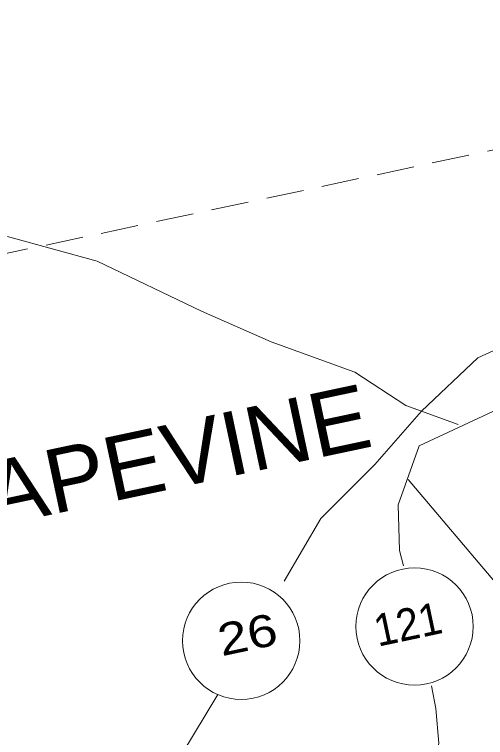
# Model space of a CAD drawing. Extents: x 2357218 to 2371708, y 6973728 to 6980157.
# Drawn here: x 2357522.9 to 2357598.1, y 6974748.1 to 6974863.5 of the extents above; entities that cross this region are included whole.
import ezdxf

# ---------------------------------------------------------------- set-up
doc = ezdxf.new("R2010")
doc.units = 0
doc.header["$LTSCALE"] = 2
doc.linetypes.add('MEDIUM_DASHED', pattern=[4.5, 3, -1.5])
doc.layers.add('62', color=7, linetype='Continuous', lineweight=13)
doc.layers.add('63', color=7, linetype='Continuous', lineweight=13)

msp = doc.modelspace()

# ---------------------------------------------------------------- linework, layer by layer
at = {"layer": '62', "linetype": 'MEDIUM_DASHED'}
msp.add_line((2357701.055, 6974863.476), (2357262.587, 6974770.278), dxfattribs=at)
at = {"layer": '62'}
for p, q in [((2357585.353, 6974801.086), (2357593.684, 6974798.028)), ((2357571.802, 6974783.024), (2357565.912, 6974773.052)), ((2357584.311, 6974777.953), (2357584.969, 6974775.514)), ((2357590.131, 6974752.736), (2357589.44, 6974756.316)), ((2357548.716, 6974744.002), (2357555.342, 6974754.934))]:
    msp.add_line(p, q, dxfattribs=at)
for points in [[(2357316.634, 6974822.183), (2357325.977, 6974829.21), (2357339.57, 6974833.985), (2357356.843, 6974830.109), (2357367.736, 6974831.46), (2357382.508, 6974827.444), (2357392.662, 6974824.794), (2357401.195, 6974823.527), (2357412.755, 6974823.776), (2357421.962, 6974824.837), (2357433.942, 6974826.923), (2357447.739, 6974830.408), (2357465.936, 6974831.929), (2357477.637, 6974833.588), (2357491.11, 6974834.819), (2357506.983, 6974831.471), (2357522.127, 6974827.953), (2357536.104, 6974824.115), (2357552.75, 6974816.152), (2357563.852, 6974811.216), (2357577.192, 6974806.369), (2357585.353, 6974801.086)], [(2357587.853, 6974800.146), (2357596.85, 6974808.683), (2357603.892, 6974811.906), (2357617.998, 6974823.047)], [(2357587.457, 6974794.656), (2357600.015, 6974800.5), (2357616.764, 6974801.254)], [(2357587.853, 6974800.146), (2357580.391, 6974791.637), (2357571.802, 6974783.024)], [(2357584.311, 6974777.953), (2357584.122, 6974785.231), (2357587.457, 6974794.656)], [(2357612.906, 6974746.026), (2357600.131, 6974772.25), (2357585.724, 6974789.274)], [(2357589.228, 6974739.131), (2357590.624, 6974747.179), (2357590.131, 6974752.736)]]:
    msp.add_lwpolyline(points, dxfattribs=at)
for centre in [(2357586.735, 6974765.808), (2357559.076, 6974763.534)]:
    msp.add_circle(centre, 9.364, dxfattribs=at)
at = {"layer": '63', "linetype": 'MEDIUM_DASHED'}
msp.add_line((2357701.055, 6974863.476), (2357262.587, 6974770.278), dxfattribs=at)
at = {"layer": '63'}
for p, q in [((2357585.353, 6974801.086), (2357593.684, 6974798.028)), ((2357571.802, 6974783.024), (2357565.912, 6974773.052)), ((2357584.311, 6974777.953), (2357584.969, 6974775.514)), ((2357590.131, 6974752.736), (2357589.44, 6974756.316)), ((2357548.716, 6974744.002), (2357555.342, 6974754.934))]:
    msp.add_line(p, q, dxfattribs=at)
for points in [[(2357316.634, 6974822.183), (2357325.977, 6974829.21), (2357339.57, 6974833.985), (2357356.843, 6974830.109), (2357367.736, 6974831.46), (2357382.508, 6974827.444), (2357392.662, 6974824.794), (2357401.195, 6974823.527), (2357412.755, 6974823.776), (2357421.962, 6974824.837), (2357433.942, 6974826.923), (2357447.739, 6974830.408), (2357465.936, 6974831.929), (2357477.637, 6974833.588), (2357491.11, 6974834.819), (2357506.983, 6974831.471), (2357522.127, 6974827.953), (2357536.104, 6974824.115), (2357552.75, 6974816.152), (2357563.852, 6974811.216), (2357577.192, 6974806.369), (2357585.353, 6974801.086)], [(2357587.853, 6974800.146), (2357596.85, 6974808.683), (2357603.892, 6974811.906), (2357617.998, 6974823.047)], [(2357587.457, 6974794.656), (2357600.015, 6974800.5), (2357616.764, 6974801.254)], [(2357587.853, 6974800.146), (2357580.391, 6974791.637), (2357571.802, 6974783.024)], [(2357584.311, 6974777.953), (2357584.122, 6974785.231), (2357587.457, 6974794.656)], [(2357612.906, 6974746.026), (2357600.131, 6974772.25), (2357585.724, 6974789.274)], [(2357589.228, 6974739.131), (2357590.624, 6974747.179), (2357590.131, 6974752.736)]]:
    msp.add_lwpolyline(points, dxfattribs=at)
for centre in [(2357586.735, 6974765.808), (2357559.076, 6974763.534)]:
    msp.add_circle(centre, 9.364, dxfattribs=at)

# ---------------------------------------------------------------- texts
at = {"layer": '62'}
for s, height, width, p in [('GRAPEVINE', 10.21, 1.05, (2357498.585, 6974777.239)), ('121', 5.099, 0.95, (2357580.889, 6974762.572)), ('26', 5.099, 1.25, (2357555.951, 6974761.045))]:
    msp.add_text(s, height=height, rotation=12, dxfattribs=dict(at, width=width)).set_placement(p)
at = {"layer": '63'}
for s, height, width, p in [('GRAPEVINE', 10.21, 1.05, (2357498.585, 6974777.239)), ('121', 5.099, 0.95, (2357580.889, 6974762.572)), ('26', 5.099, 1.25, (2357555.951, 6974761.045))]:
    msp.add_text(s, height=height, rotation=12, dxfattribs=dict(at, width=width)).set_placement(p)

doc.saveas('drawing.dxf')
